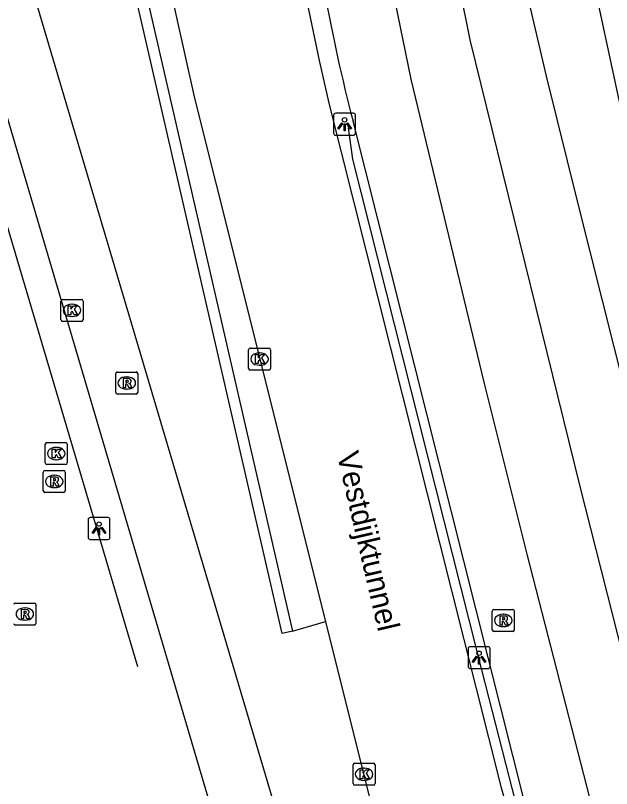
# Model space of a CAD drawing. Extents: x 160806 to 161707, y 383697 to 384148.
# Drawn here: x 161236.93 to 161264.04, y 383783.17 to 383818.32 of the extents above; entities that cross this region are included whole.
import ezdxf

# ---------------------------------------------------------------- set-up
doc = ezdxf.new("R2010")
doc.units = 0
for name, color, linetype in [('IMGEO_Fietspad_open', 7, 'Continuous'), ('IMGEO_Hek', 7, 'Continuous'), ('IMGEO_Kolk', 7, 'Continuous'), ('IMGEO_Lichtpunt', 7, 'Continuous'), ('IMGEO_Muur', 7, 'Continuous'), ('IMGEO_Openbare_ruimte_label', 7, 'Continuous'), ('IMGEO_Rijbaan_lokaal_gesloten', 7, 'Continuous'), ('IMGEO_Rioolput', 7, 'Continuous'), ('IMGEO_Voetpad_open', 7, 'Continuous')]:
    doc.layers.add(name, color=color, linetype=linetype)

msp = doc.modelspace()

# ---------------------------------------------------------------- linework, layer by layer
at = {"layer": 'IMGEO_Fietspad_open'}
for points in [[(161258.147, 383763.342), (161250.185, 383777.467), (161232.095, 383838.372)], [(161229.906, 383836.178), (161247.443, 383776.827)]]:
    msp.add_lwpolyline(points, dxfattribs=at)
at = {"layer": 'IMGEO_Hek'}
for points in [[(161257.937, 383789.343), (161252.272, 383811.783), (161252.082, 383813.215)], [(161265.912, 383764.193), (161262.514, 383773.318), (161260.283, 383780.231), (161258.466, 383787.267), (161257.937, 383789.343)]]:
    msp.add_lwpolyline(points, dxfattribs=at)
at = {"layer": 'IMGEO_Kolk'}
for p, q in [((161239.005, 383804.487), (161239.005, 383805.339)), ((161239.08, 383805.413), (161239.932, 383805.413)), ((161240.006, 383805.339), (161240.006, 383804.487)), ((161239.493, 383805.193), (161239.518, 383805.193)), ((161239.932, 383804.413), (161239.08, 383804.413)), ((161239.516, 383804.633), (161239.491, 383804.633)), ((161247.533, 383802.274), (161247.533, 383803.126)), ((161247.608, 383803.2), (161248.46, 383803.2)), ((161248.021, 383802.98), (161248.046, 383802.98)), ((161248.534, 383803.126), (161248.534, 383802.274)), ((161248.46, 383802.2), (161247.608, 383802.2)), ((161248.044, 383802.42), (161248.019, 383802.42)), ((161238.289, 383797.978), (161238.289, 383798.83)), ((161238.364, 383798.904), (161239.216, 383798.904)), ((161238.777, 383798.684), (161238.802, 383798.684)), ((161239.29, 383798.83), (161239.29, 383797.978)), ((161238.8, 383798.124), (161238.775, 383798.124)), ((161239.216, 383797.904), (161238.364, 383797.904)), ((161252.361, 383784.323), (161253.213, 383784.323)), ((161252.286, 383783.397), (161252.286, 383784.249)), ((161252.774, 383784.103), (161252.799, 383784.103)), ((161253.287, 383784.249), (161253.287, 383783.397)), ((161253.213, 383783.323), (161252.361, 383783.323)), ((161252.797, 383783.543), (161252.772, 383783.543))]:
    msp.add_line(p, q, dxfattribs=at)
for points in [[(161239.005, 383804.487), (161239.005, 383805.339)], [(161239.08, 383805.413), (161239.932, 383805.413)], [(161240.006, 383805.339), (161240.006, 383804.487)], [(161239.326, 383805.113), (161239.449, 383805.113), (161239.449, 383804.962), (161239.579, 383805.113), (161239.743, 383805.113), (161239.597, 383804.962), (161239.75, 383804.713), (161239.598, 383804.713), (161239.513, 383804.877), (161239.449, 383804.81), (161239.449, 383804.713), (161239.326, 383804.713), (161239.326, 383805.113)], [(161239.932, 383804.413), (161239.08, 383804.413)], [(161247.533, 383802.274), (161247.533, 383803.126)], [(161247.608, 383803.2), (161248.46, 383803.2)], [(161247.854, 383802.9), (161247.977, 383802.9), (161247.977, 383802.749), (161248.107, 383802.9), (161248.271, 383802.9), (161248.125, 383802.749), (161248.278, 383802.5), (161248.126, 383802.5), (161248.041, 383802.664), (161247.977, 383802.597), (161247.977, 383802.5), (161247.854, 383802.5), (161247.854, 383802.9)], [(161248.534, 383803.126), (161248.534, 383802.274)], [(161248.46, 383802.2), (161247.608, 383802.2)], [(161238.289, 383797.978), (161238.289, 383798.83)], [(161238.364, 383798.904), (161239.216, 383798.904)], [(161239.29, 383798.83), (161239.29, 383797.978)], [(161238.61, 383798.604), (161238.733, 383798.604), (161238.733, 383798.453), (161238.863, 383798.604), (161239.027, 383798.604), (161238.881, 383798.453), (161239.034, 383798.204), (161238.882, 383798.204), (161238.797, 383798.368), (161238.733, 383798.301), (161238.733, 383798.204), (161238.61, 383798.204), (161238.61, 383798.604)], [(161239.216, 383797.904), (161238.364, 383797.904)], [(161252.361, 383784.323), (161253.213, 383784.323)], [(161252.286, 383783.397), (161252.286, 383784.249)], [(161252.607, 383784.023), (161252.73, 383784.023), (161252.73, 383783.872), (161252.86, 383784.023), (161253.024, 383784.023), (161252.878, 383783.872), (161253.031, 383783.623), (161252.879, 383783.623), (161252.794, 383783.787), (161252.73, 383783.72), (161252.73, 383783.623), (161252.607, 383783.623), (161252.607, 383784.023)], [(161253.287, 383784.249), (161253.287, 383783.397)], [(161253.213, 383783.323), (161252.361, 383783.323)]]:
    msp.add_lwpolyline(points, dxfattribs=at)
for centre, start, end in [((161239.082, 383805.337), 91.552, 178.448), ((161239.082, 383805.337), 91.552, 178.448), ((161239.93, 383805.337), 1.552, 88.448), ((161239.93, 383805.337), 1.552, 88.448), ((161239.082, 383804.489), 181.552, 268.448), ((161239.082, 383804.489), 181.552, 268.448), ((161239.93, 383804.489), 271.552, 358.448), ((161239.93, 383804.489), 271.552, 358.448), ((161247.61, 383803.124), 91.552, 178.448), ((161247.61, 383803.124), 91.552, 178.448), ((161248.458, 383803.124), 1.552, 88.448), ((161248.458, 383803.124), 1.552, 88.448), ((161247.61, 383802.276), 181.552, 268.448), ((161247.61, 383802.276), 181.552, 268.448), ((161248.458, 383802.276), 271.552, 358.448), ((161248.458, 383802.276), 271.552, 358.448), ((161238.366, 383798.828), 91.552, 178.448), ((161238.366, 383798.828), 91.552, 178.448), ((161239.214, 383798.828), 1.552, 88.448), ((161239.214, 383798.828), 1.552, 88.448), ((161238.366, 383797.98), 181.552, 268.448), ((161238.366, 383797.98), 181.552, 268.448), ((161239.214, 383797.98), 271.552, 358.448), ((161239.214, 383797.98), 271.552, 358.448), ((161252.363, 383784.247), 91.552, 178.448), ((161252.363, 383784.247), 91.552, 178.448), ((161253.211, 383784.247), 1.552, 88.448), ((161253.211, 383784.247), 1.552, 88.448), ((161252.363, 383783.399), 181.552, 268.448), ((161252.363, 383783.399), 181.552, 268.448), ((161253.211, 383783.399), 271.552, 358.448), ((161253.211, 383783.399), 271.552, 358.448)]:
    msp.add_arc(centre, 0.0765, start, end, dxfattribs=at)
for centre, major_axis, ratio, start_param, end_param in [((161239.492, 383804.913), (-0.387, 0.002), 0.722429, 4.712389, 7.853982), ((161239.517, 383804.913), (-0.39, 0.002), 0.717154, 1.570796, 4.712389), ((161248.02, 383802.7), (-0.387, 0.002), 0.722429, 4.712389, 7.853982), ((161248.045, 383802.7), (-0.39, 0.002), 0.717154, 1.570796, 4.712389), ((161238.776, 383798.404), (-0.387, 0.002), 0.722429, 4.712389, 7.853982), ((161238.801, 383798.404), (-0.39, 0.002), 0.717154, 1.570796, 4.712389), ((161252.773, 383783.823), (-0.387, 0.002), 0.722429, 4.712389, 7.853982), ((161252.798, 383783.823), (-0.39, 0.002), 0.717154, 1.570796, 4.712389)]:
    msp.add_ellipse(centre, major_axis=major_axis, ratio=ratio, start_param=start_param, end_param=end_param, dxfattribs=at)
at = {"layer": 'IMGEO_Lichtpunt'}
for p, q in [((161251.401, 383813.778), (161251.401, 383812.971)), ((161251.401, 383813.778), (161251.401, 383812.971)), ((161252.303, 383813.873), (161251.495, 383813.873)), ((161252.303, 383813.873), (161251.495, 383813.873)), ((161252.397, 383812.971), (161252.397, 383813.778)), ((161252.397, 383812.971), (161252.397, 383813.778)), ((161251.495, 383812.877), (161252.303, 383812.877)), ((161251.495, 383812.877), (161252.303, 383812.877)), ((161240.237, 383795.4), (161240.237, 383794.593)), ((161240.237, 383795.4), (161240.237, 383794.593)), ((161241.139, 383795.495), (161240.331, 383795.495)), ((161241.139, 383795.495), (161240.331, 383795.495)), ((161241.233, 383794.593), (161241.233, 383795.4)), ((161241.233, 383794.593), (161241.233, 383795.4)), ((161240.331, 383794.499), (161241.139, 383794.499)), ((161240.331, 383794.499), (161241.139, 383794.499)), ((161257.518, 383789.529), (161257.518, 383788.722)), ((161257.518, 383789.529), (161257.518, 383788.722)), ((161258.42, 383789.624), (161257.612, 383789.624)), ((161258.42, 383789.624), (161257.612, 383789.624)), ((161258.514, 383788.722), (161258.514, 383789.529)), ((161258.514, 383788.722), (161258.514, 383789.529)), ((161257.612, 383788.628), (161258.42, 383788.628)), ((161257.612, 383788.628), (161258.42, 383788.628))]:
    msp.add_line(p, q, dxfattribs=at)
for points in [[(161251.775, 383813.442), (161251.814, 383813.414), (161251.626, 383813.152), (161251.588, 383813.179), (161251.775, 383813.442)], [(161251.987, 383813.414), (161252.025, 383813.441), (161252.212, 383813.179), (161252.173, 383813.151), (161251.987, 383813.414)], [(161251.877, 383813.394), (161251.924, 383813.394), (161251.924, 383813.072), (161251.877, 383813.072), (161251.877, 383813.394)], [(161240.611, 383795.064), (161240.65, 383795.036), (161240.462, 383794.774), (161240.424, 383794.801), (161240.611, 383795.064)], [(161240.713, 383795.016), (161240.76, 383795.016), (161240.76, 383794.694), (161240.713, 383794.694), (161240.713, 383795.016)], [(161240.823, 383795.036), (161240.861, 383795.063), (161241.048, 383794.801), (161241.009, 383794.773), (161240.823, 383795.036)], [(161257.892, 383789.193), (161257.931, 383789.165), (161257.743, 383788.903), (161257.705, 383788.93), (161257.892, 383789.193)], [(161258.104, 383789.165), (161258.142, 383789.192), (161258.329, 383788.93), (161258.29, 383788.902), (161258.104, 383789.165)], [(161257.994, 383789.145), (161258.041, 383789.145), (161258.041, 383788.823), (161257.994, 383788.823), (161257.994, 383789.145)]]:
    msp.add_lwpolyline(points, dxfattribs=at)
for centre in [(161251.9, 383813.576), (161240.736, 383795.198), (161258.017, 383789.327)]:
    msp.add_circle(centre, 0.0994, dxfattribs=at)
for centre, start, end in [((161251.495, 383813.778), 90, 180), ((161251.495, 383813.778), 90, 180), ((161252.303, 383813.778), 0, 90), ((161252.303, 383813.778), 0, 90), ((161251.495, 383812.971), 180, 270), ((161251.495, 383812.971), 180, 270), ((161252.303, 383812.971), 270, 0), ((161252.303, 383812.971), 270, 360), ((161240.331, 383795.4), 90, 180), ((161240.331, 383795.4), 90, 180), ((161241.139, 383795.4), 0, 90), ((161241.139, 383795.4), 0, 90), ((161240.331, 383794.593), 180, 270), ((161240.331, 383794.593), 180, 270), ((161241.139, 383794.593), 270, 0), ((161241.139, 383794.593), 270, 360), ((161257.612, 383789.529), 90, 180), ((161257.612, 383789.529), 90, 180), ((161258.42, 383789.529), 0, 90), ((161258.42, 383789.529), 0, 90), ((161257.612, 383788.722), 180, 270), ((161257.612, 383788.722), 180, 270), ((161258.42, 383788.722), 270, 0), ((161258.42, 383788.722), 270, 360)]:
    msp.add_arc(centre, 0.0946, start, end, dxfattribs=at)
at = {"layer": 'IMGEO_Muur'}
for points in [[(161238.694, 383839.54), (161239.237, 383837.58), (161242.274, 383821.936), (161249.537, 383790.335)], [(161249.537, 383790.335), (161249.06, 383790.222), (161241.78, 383821.883), (161238.738, 383837.463), (161238.211, 383839.391)], [(161228.446, 383835.728), (161228.783, 383834.579), (161235.658, 383811.717), (161242.485, 383788.73)]]:
    msp.add_lwpolyline(points, dxfattribs=at)
at = {"layer": 'IMGEO_Rijbaan_lokaal_gesloten'}
for points in [[(161266.67, 383803.83), (161261.458, 383828.087), (161260.887, 383830.892), (161259.905, 383835.909), (161258.808, 383841.755), (161258.098, 383845.532)], [(161272.703, 383771.417), (161271.69, 383774.162), (161268.422, 383786.436), (161264.696, 383801.082), (161262.513, 383809.751), (161261.079, 383815.554), (161260.191, 383819.388), (161259.009, 383825.191), (161255.351, 383843.932), (161255.223, 383844.644)], [(161252.374, 383843.765), (161253.35, 383838.619), (161254.467, 383832.736), (161257.59, 383817.205), (161262.593, 383796.907), (161267.226, 383778.65), (161272.066, 383761.555), (161275.575, 383751.679)], [(161272.079, 383751.073), (161271.27, 383753.915), (161267.992, 383764.419), (161264.266, 383778.033), (161260.199, 383793.827), (161258.251, 383801.656), (161254.931, 383815.431), (161252.101, 383829.184), (161249.639, 383841.943), (161249.469, 383842.867)], [(161245.391, 383841.608), (161245.836, 383839.778), (161250.747, 383816.268), (161251.189, 383814.332), (161259.008, 383783.268)], [(161239.635, 383839.831), (161240.829, 383834.589), (161244.197, 383818.504), (161245.074, 383814.567), (161246.038, 383810.692), (161251.033, 383790.764)], [(161263.566, 383772.013), (161260.992, 383779.593), (161260.508, 383781.031), (161260.112, 383782.451), (161252.284, 383813.518)], [(161251.033, 383790.764), (161253.161, 383782.273)]]:
    msp.add_lwpolyline(points, dxfattribs=at)
for centre, radius, start, end in [((161323.536, 383832.245), 73.672, 190.04698, 194.72543), ((161409.035, 383822.146), 154.982, 194.528, 199.70274)]:
    msp.add_arc(centre, radius, start, end, dxfattribs=at)
at = {"layer": 'IMGEO_Rioolput'}
for p, q in [((161241.497, 383801.185), (161241.497, 383802.037)), ((161241.572, 383802.111), (161242.424, 383802.111)), ((161241.985, 383801.891), (161242.01, 383801.891)), ((161242.498, 383802.037), (161242.498, 383801.185)), ((161242.008, 383801.331), (161241.983, 383801.331)), ((161242.424, 383801.111), (161241.572, 383801.111)), ((161238.273, 383797.635), (161239.125, 383797.635)), ((161238.198, 383796.709), (161238.198, 383797.561)), ((161238.686, 383797.415), (161238.711, 383797.415)), ((161239.199, 383797.561), (161239.199, 383796.709)), ((161239.125, 383796.635), (161238.273, 383796.635)), ((161238.709, 383796.855), (161238.684, 383796.855)), ((161236.935, 383791.608), (161237.787, 383791.608)), ((161237.348, 383791.388), (161237.373, 383791.388)), ((161237.861, 383791.534), (161237.861, 383790.682)), ((161258.691, 383791.318), (161259.543, 383791.318)), ((161258.616, 383790.392), (161258.616, 383791.244)), ((161259.104, 383791.098), (161259.129, 383791.098)), ((161259.617, 383791.244), (161259.617, 383790.392)), ((161237.787, 383790.608), (161236.935, 383790.608)), ((161237.371, 383790.828), (161237.346, 383790.828)), ((161259.543, 383790.318), (161258.691, 383790.318)), ((161259.127, 383790.538), (161259.102, 383790.538))]:
    msp.add_line(p, q, dxfattribs=at)
for points in [[(161241.497, 383801.185), (161241.497, 383802.037)], [(161241.572, 383802.111), (161242.424, 383802.111)], [(161242.498, 383802.037), (161242.498, 383801.185)], [(161242.086, 383801.809), (161241.834, 383801.811), (161241.834, 383801.411)], [(161241.834, 383801.411), (161241.958, 383801.411), (161241.958, 383801.573), (161241.969, 383801.573)], [(161242.012, 383801.73), (161241.958, 383801.73), (161241.958, 383801.649)], [(161241.958, 383801.649), (161242.01, 383801.649)], [(161242.016, 383801.544), (161242.087, 383801.411), (161242.227, 383801.411), (161242.162, 383801.537)], [(161242.424, 383801.111), (161241.572, 383801.111)], [(161238.273, 383797.635), (161239.125, 383797.635)], [(161238.198, 383796.709), (161238.198, 383797.561)], [(161238.787, 383797.333), (161238.535, 383797.335), (161238.535, 383796.935)], [(161239.199, 383797.561), (161239.199, 383796.709)], [(161238.535, 383796.935), (161238.659, 383796.935), (161238.659, 383797.097), (161238.67, 383797.097)], [(161238.713, 383797.254), (161238.659, 383797.254), (161238.659, 383797.173)], [(161238.659, 383797.173), (161238.711, 383797.173)], [(161238.717, 383797.068), (161238.788, 383796.935), (161238.928, 383796.935), (161238.863, 383797.061)], [(161239.125, 383796.635), (161238.273, 383796.635)], [(161236.935, 383791.608), (161237.787, 383791.608)], [(161237.449, 383791.306), (161237.197, 383791.308), (161237.197, 383790.908)], [(161237.861, 383791.534), (161237.861, 383790.682)], [(161258.691, 383791.318), (161259.543, 383791.318)], [(161237.197, 383790.908), (161237.321, 383790.908), (161237.321, 383791.07), (161237.332, 383791.07)], [(161237.375, 383791.227), (161237.321, 383791.227), (161237.321, 383791.146)], [(161237.321, 383791.146), (161237.373, 383791.146)], [(161237.379, 383791.041), (161237.45, 383790.908), (161237.59, 383790.908), (161237.525, 383791.034)], [(161258.616, 383790.392), (161258.616, 383791.244)], [(161259.205, 383791.016), (161258.953, 383791.018), (161258.953, 383790.618)], [(161259.131, 383790.937), (161259.077, 383790.937), (161259.077, 383790.856)], [(161259.617, 383791.244), (161259.617, 383790.392)], [(161237.787, 383790.608), (161236.935, 383790.608)], [(161258.953, 383790.618), (161259.077, 383790.618), (161259.077, 383790.78), (161259.088, 383790.78)], [(161259.077, 383790.856), (161259.129, 383790.856)], [(161259.135, 383790.751), (161259.206, 383790.618), (161259.346, 383790.618), (161259.281, 383790.744)], [(161259.543, 383790.318), (161258.691, 383790.318)]]:
    msp.add_lwpolyline(points, dxfattribs=at)
for centre, radius, start, end in [((161241.574, 383802.035), 0.0765, 91.552, 178.448), ((161241.574, 383802.035), 0.0765, 91.552, 178.448), ((161242.422, 383802.035), 0.0765, 1.552, 88.448), ((161242.422, 383802.035), 0.0765, 1.552, 88.448), ((161241.968, 383801.52), 0.0533, 26.0293, 88.6989), ((161241.994, 383801.838), 0.19, 274.7715, 282.9687), ((161242.018, 383801.634), 0.0964, 77.0061, 93.1865), ((161242.032, 383801.691), 0.0378, 276.6634, 79.6772), ((161242.085, 383801.699), 0.109, 350.3612, 89.416), ((161242.083, 383801.699), 0.112, 277.5842, 350.9817), ((161242.067, 383801.484), 0.108, 29.5134, 73.7905), ((161241.574, 383801.187), 0.0765, 181.552, 268.448), ((161241.574, 383801.187), 0.0765, 181.552, 268.448), ((161242.422, 383801.187), 0.0765, 271.552, 358.448), ((161242.422, 383801.187), 0.0765, 271.552, 358.448), ((161238.275, 383797.559), 0.0765, 91.552, 178.448), ((161238.275, 383797.559), 0.0765, 91.552, 178.448), ((161239.123, 383797.559), 0.0765, 1.552, 88.448), ((161239.123, 383797.559), 0.0765, 1.552, 88.448), ((161238.719, 383797.158), 0.0964, 77.0061, 93.1865), ((161238.786, 383797.223), 0.109, 350.3612, 89.416), ((161238.669, 383797.044), 0.0533, 26.0293, 88.6989), ((161238.695, 383797.362), 0.19, 274.7715, 282.9687), ((161238.733, 383797.215), 0.0378, 276.6634, 79.6772), ((161238.784, 383797.223), 0.112, 277.5842, 350.9817), ((161238.768, 383797.008), 0.108, 29.5134, 73.7905), ((161238.275, 383796.711), 0.0765, 181.552, 268.448), ((161238.275, 383796.711), 0.0765, 181.552, 268.448), ((161239.123, 383796.711), 0.0765, 271.552, 358.448), ((161239.123, 383796.711), 0.0765, 271.552, 358.448), ((161236.937, 383791.532), 0.0765, 91.552, 178.448), ((161236.937, 383791.532), 0.0765, 91.552, 178.448), ((161237.448, 383791.196), 0.109, 350.3612, 89.416), ((161237.785, 383791.532), 0.0765, 1.552, 88.448), ((161237.785, 383791.532), 0.0765, 1.552, 88.448), ((161258.693, 383791.242), 0.0765, 91.552, 178.448), ((161258.693, 383791.242), 0.0765, 91.552, 178.448), ((161259.541, 383791.242), 0.0765, 1.552, 88.448), ((161259.541, 383791.242), 0.0765, 1.552, 88.448), ((161237.331, 383791.017), 0.0533, 26.0293, 88.6989), ((161237.357, 383791.335), 0.19, 274.7715, 282.9687), ((161237.381, 383791.131), 0.0964, 77.0061, 93.1865), ((161237.395, 383791.188), 0.0378, 276.6634, 79.6772), ((161237.446, 383791.196), 0.112, 277.5842, 350.9817), ((161237.43, 383790.981), 0.108, 29.5134, 73.7905), ((161259.137, 383790.841), 0.0964, 77.0061, 93.1865), ((161259.151, 383790.898), 0.0378, 276.6634, 79.6772), ((161259.204, 383790.906), 0.109, 350.3612, 89.416), ((161236.937, 383790.684), 0.0765, 181.552, 268.448), ((161236.937, 383790.684), 0.0765, 181.552, 268.448), ((161237.785, 383790.684), 0.0765, 271.552, 358.448), ((161237.785, 383790.684), 0.0765, 271.552, 358.448), ((161259.087, 383790.727), 0.0533, 26.0293, 88.6989), ((161259.113, 383791.045), 0.19, 274.7715, 282.9687), ((161259.202, 383790.906), 0.112, 277.5842, 350.9817), ((161259.186, 383790.691), 0.108, 29.5134, 73.7905), ((161258.693, 383790.394), 0.0765, 181.552, 268.448), ((161258.693, 383790.394), 0.0765, 181.552, 268.448), ((161259.541, 383790.394), 0.0765, 271.552, 358.448), ((161259.541, 383790.394), 0.0765, 271.552, 358.448)]:
    msp.add_arc(centre, radius, start, end, dxfattribs=at)
for centre, major_axis, ratio, start_param, end_param in [((161241.984, 383801.611), (-0.387, 0.002), 0.722429, 4.712389, 7.853982), ((161242.009, 383801.611), (-0.39, 0.002), 0.717154, 1.570796, 4.712389), ((161238.685, 383797.135), (-0.387, 0.002), 0.722429, 4.712389, 7.853982), ((161238.71, 383797.135), (-0.39, 0.002), 0.717154, 1.570796, 4.712389), ((161237.347, 383791.108), (-0.387, 0.002), 0.722429, 4.712389, 7.853982), ((161237.372, 383791.108), (-0.39, 0.002), 0.717154, 1.570796, 4.712389), ((161259.103, 383790.818), (-0.387, 0.002), 0.722429, 4.712389, 7.853982), ((161259.128, 383790.818), (-0.39, 0.002), 0.717154, 1.570796, 4.712389)]:
    msp.add_ellipse(centre, major_axis=major_axis, ratio=ratio, start_param=start_param, end_param=end_param, dxfattribs=at)
at = {"layer": 'IMGEO_Voetpad_open'}
msp.add_lwpolyline([(161249.537, 383790.335), (161251.033, 383790.764)], dxfattribs=at)

# ---------------------------------------------------------------- texts
at = {"layer": 'IMGEO_Openbare_ruimte_label'}
msp.add_text('Vestdijktunnel', height=1, rotation=283.1191, dxfattribs=at).set_placement((161251.547, 383798.367))

doc.saveas('drawing.dxf')
